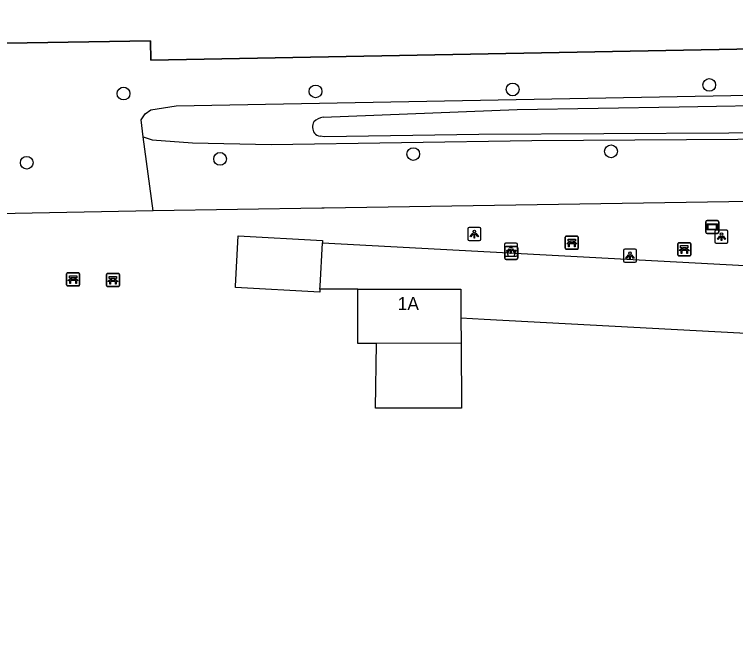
# Model space of a CAD drawing. Extents: x 161761 to 162722, y 384793 to 385405.
# Drawn here: x 162200.7 to 162256.1, y 385305.9 to 385354.5 of the extents above; entities that cross this region are included whole.
import ezdxf

# ---------------------------------------------------------------- set-up
doc = ezdxf.new("R2010")
doc.units = 0
for name, color, linetype in [('IMGEO_Afvalbak', 7, 'Continuous'), ('IMGEO_Bank', 7, 'Continuous'), ('IMGEO_Boom', 7, 'Continuous'), ('IMGEO_Groenvoorziening', 7, 'Continuous'), ('IMGEO_Hek', 7, 'Continuous'), ('IMGEO_Lichtpunt', 7, 'Continuous'), ('IMGEO_Pand', 7, 'Continuous'), ('IMGEO_Pand_nummerreeks', 7, 'Continuous'), ('IMGEO_Verklikker', 7, 'Continuous'), ('IMGEO_Voetpad_open', 7, 'Continuous'), ('IMGEO_Waterloop', 7, 'Continuous')]:
    doc.layers.add(name, color=color, linetype=linetype)

msp = doc.modelspace()

# ---------------------------------------------------------------- linework, layer by layer
at = {"layer": 'IMGEO_Afvalbak'}
for p, q in [((162238.362, 385335.756), (162238.362, 385336.556)), ((162238.362, 385336.556), (162238.362, 385335.756)), ((162238.462, 385336.656), (162239.252, 385336.656)), ((162239.252, 385336.656), (162238.462, 385336.656)), ((162239.352, 385336.556), (162239.352, 385335.756)), ((162239.352, 385335.756), (162239.352, 385336.556)), ((162239.252, 385335.656), (162238.462, 385335.656)), ((162238.462, 385335.656), (162239.252, 385335.656))]:
    msp.add_line(p, q, dxfattribs=at)
msp.add_lwpolyline([(162238.505, 385336.37), (162239.209, 385336.37), (162239.06, 385335.9), (162238.654, 385335.9), (162238.505, 385336.37)], dxfattribs=at)
for centre, start, end in [((162238.462, 385336.556), 90, 180), ((162238.462, 385336.556), 90, 180), ((162239.252, 385336.556), 0, 90), ((162239.252, 385336.556), 360, 90), ((162238.462, 385335.756), 180, 270), ((162238.462, 385335.756), 180, 270), ((162239.252, 385335.756), 270, 0), ((162239.252, 385335.756), 270, 0)]:
    msp.add_arc(centre, 0.1, start, end, dxfattribs=at)
at = {"layer": 'IMGEO_Bank'}
for p, q in [((162243.01, 385336.531), (162243.01, 385337.372)), ((162243.01, 385337.372), (162243.01, 385336.531)), ((162243.085, 385337.456), (162243.926, 385337.456)), ((162243.926, 385337.456), (162243.085, 385337.456)), ((162243.319, 385336.962), (162243.319, 385337.068)), ((162243.363, 385337.068), (162243.363, 385336.962)), ((162243.651, 385337.074), (162243.369, 385337.074)), ((162243.369, 385336.956), (162243.651, 385336.956)), ((162243.657, 385336.962), (162243.657, 385337.068)), ((162243.701, 385337.068), (162243.701, 385336.962)), ((162244.01, 385337.381), (162244.01, 385336.54)), ((162244.01, 385336.54), (162244.01, 385337.381)), ((162251.735, 385336.946), (162252.576, 385336.946)), ((162252.576, 385336.946), (162251.735, 385336.946)), ((162243.935, 385336.456), (162243.094, 385336.456)), ((162243.094, 385336.456), (162243.935, 385336.456)), ((162243.707, 385336.854), (162243.314, 385336.854)), ((162251.66, 385336.021), (162251.66, 385336.862)), ((162251.66, 385336.862), (162251.66, 385336.021)), ((162251.969, 385336.452), (162251.969, 385336.558)), ((162252.013, 385336.558), (162252.013, 385336.452)), ((162252.301, 385336.564), (162252.019, 385336.564)), ((162252.019, 385336.446), (162252.301, 385336.446)), ((162252.307, 385336.452), (162252.307, 385336.558)), ((162252.351, 385336.558), (162252.351, 385336.452)), ((162252.66, 385336.871), (162252.66, 385336.03)), ((162252.66, 385336.03), (162252.66, 385336.871)), ((162252.585, 385335.946), (162251.744, 385335.946)), ((162251.744, 385335.946), (162252.585, 385335.946)), ((162252.357, 385336.344), (162251.964, 385336.344)), ((162204.681, 385333.714), (162204.681, 385334.555)), ((162204.681, 385334.555), (162204.681, 385333.714)), ((162204.756, 385334.639), (162205.597, 385334.639)), ((162205.597, 385334.639), (162204.756, 385334.639)), ((162204.99, 385334.145), (162204.99, 385334.251)), ((162205.034, 385334.251), (162205.034, 385334.145)), ((162205.322, 385334.257), (162205.04, 385334.257)), ((162205.04, 385334.139), (162205.322, 385334.139)), ((162205.328, 385334.145), (162205.328, 385334.251)), ((162205.372, 385334.251), (162205.372, 385334.145)), ((162205.681, 385334.564), (162205.681, 385333.723)), ((162205.681, 385333.723), (162205.681, 385334.564)), ((162207.744, 385333.657), (162207.744, 385334.498)), ((162207.744, 385334.498), (162207.744, 385333.657)), ((162207.819, 385334.582), (162208.66, 385334.582)), ((162208.66, 385334.582), (162207.819, 385334.582)), ((162208.053, 385334.088), (162208.053, 385334.194)), ((162208.097, 385334.194), (162208.097, 385334.088)), ((162208.385, 385334.2), (162208.103, 385334.2)), ((162208.391, 385334.088), (162208.391, 385334.194)), ((162208.435, 385334.194), (162208.435, 385334.088)), ((162208.744, 385334.507), (162208.744, 385333.666)), ((162208.744, 385333.666), (162208.744, 385334.507)), ((162205.606, 385333.639), (162204.765, 385333.639)), ((162204.765, 385333.639), (162205.606, 385333.639)), ((162205.378, 385334.037), (162204.985, 385334.037)), ((162208.441, 385333.98), (162208.048, 385333.98)), ((162208.103, 385334.082), (162208.385, 385334.082)), ((162208.669, 385333.582), (162207.828, 385333.582)), ((162207.828, 385333.582), (162208.669, 385333.582))]:
    msp.add_line(p, q, dxfattribs=at)
for points in [[(162243.257, 385336.854), (162243.115, 385336.854), (162243.227, 385336.956), (162243.313, 385336.956)], [(162243.313, 385337.074), (162243.227, 385337.074), (162243.227, 385337.235), (162243.79, 385337.235), (162243.79, 385337.074), (162243.707, 385337.074)], [(162243.707, 385336.956), (162243.79, 385336.956), (162243.902, 385336.854), (162243.763, 385336.854)], [(162243.307, 385336.847), (162243.307, 385336.64), (162243.264, 385336.64), (162243.264, 385336.847)], [(162243.757, 385336.847), (162243.757, 385336.64), (162243.713, 385336.64), (162243.713, 385336.847)], [(162251.907, 385336.344), (162251.765, 385336.344), (162251.877, 385336.446), (162251.963, 385336.446)], [(162251.963, 385336.564), (162251.877, 385336.564), (162251.877, 385336.725), (162252.44, 385336.725), (162252.44, 385336.564), (162252.357, 385336.564)], [(162252.357, 385336.446), (162252.44, 385336.446), (162252.552, 385336.344), (162252.413, 385336.344)], [(162251.957, 385336.337), (162251.957, 385336.13), (162251.914, 385336.13), (162251.914, 385336.337)], [(162252.407, 385336.337), (162252.407, 385336.13), (162252.363, 385336.13), (162252.363, 385336.337)], [(162204.928, 385334.037), (162204.786, 385334.037), (162204.898, 385334.139), (162204.984, 385334.139)], [(162204.984, 385334.257), (162204.898, 385334.257), (162204.898, 385334.418), (162205.461, 385334.418), (162205.461, 385334.257), (162205.378, 385334.257)], [(162205.378, 385334.139), (162205.461, 385334.139), (162205.573, 385334.037), (162205.434, 385334.037)], [(162208.047, 385334.2), (162207.961, 385334.2), (162207.961, 385334.361), (162208.524, 385334.361), (162208.524, 385334.2), (162208.441, 385334.2)], [(162204.978, 385334.03), (162204.978, 385333.823), (162204.935, 385333.823), (162204.935, 385334.03)], [(162205.428, 385334.03), (162205.428, 385333.823), (162205.384, 385333.823), (162205.384, 385334.03)], [(162207.991, 385333.98), (162207.849, 385333.98), (162207.961, 385334.082), (162208.047, 385334.082)], [(162208.041, 385333.973), (162208.041, 385333.766), (162207.998, 385333.766), (162207.998, 385333.973)], [(162208.441, 385334.082), (162208.524, 385334.082), (162208.636, 385333.98), (162208.497, 385333.98)], [(162208.491, 385333.973), (162208.491, 385333.766), (162208.447, 385333.766), (162208.447, 385333.973)]]:
    msp.add_lwpolyline(points, dxfattribs=at)
for centre, radius, start, end in [((162243.088, 385337.378), 0.0779, 92.4484, 184.2845), ((162243.088, 385337.378), 0.0779, 92.4484, 184.2845), ((162243.312, 385337.067), 0.00671, 2.8957, 87.1043), ((162243.312, 385336.963), 0.00671, 272.8957, 357.1043), ((162243.369, 385337.067), 0.00671, 92.8957, 177.1043), ((162243.369, 385336.963), 0.00671, 182.8957, 267.1043), ((162243.651, 385337.067), 0.00671, 2.8957, 87.1043), ((162243.651, 385336.963), 0.00671, 272.8957, 357.1043), ((162243.708, 385337.067), 0.00671, 92.8957, 177.1043), ((162243.708, 385336.963), 0.00671, 182.8957, 267.1043), ((162243.932, 385337.378), 0.0779, 2.4484, 94.2845), ((162243.932, 385337.378), 0.0779, 2.4484, 94.2845), ((162251.738, 385336.868), 0.0779, 92.4484, 184.2845), ((162251.738, 385336.868), 0.0779, 92.4484, 184.2845), ((162252.582, 385336.868), 0.0779, 2.4484, 94.2845), ((162252.582, 385336.868), 0.0779, 2.4484, 94.2845), ((162243.088, 385336.534), 0.0779, 182.4484, 274.2845), ((162243.088, 385336.534), 0.0779, 182.4484, 274.2845), ((162243.257, 385336.847), 0.00671, 2.8957, 87.1043), ((162243.314, 385336.847), 0.00671, 92.8957, 177.1043), ((162243.706, 385336.847), 0.00671, 2.8957, 87.1043), ((162243.763, 385336.847), 0.00671, 92.8957, 177.1043), ((162243.932, 385336.534), 0.0779, 272.4484, 4.2845), ((162243.932, 385336.534), 0.0779, 272.4484, 4.2845), ((162251.962, 385336.557), 0.00671, 2.8957, 87.1043), ((162251.962, 385336.453), 0.00671, 272.8957, 357.1043), ((162252.019, 385336.557), 0.00671, 92.8957, 177.1043), ((162252.019, 385336.453), 0.00671, 182.8957, 267.1043), ((162252.301, 385336.557), 0.00671, 2.8957, 87.1043), ((162252.301, 385336.453), 0.00671, 272.8957, 357.1043), ((162252.358, 385336.557), 0.00671, 92.8957, 177.1043), ((162252.358, 385336.453), 0.00671, 182.8957, 267.1043), ((162251.738, 385336.024), 0.0779, 182.4484, 274.2845), ((162251.738, 385336.024), 0.0779, 182.4484, 274.2845), ((162251.907, 385336.337), 0.00671, 2.8957, 87.1043), ((162251.964, 385336.337), 0.00671, 92.8957, 177.1043), ((162252.356, 385336.337), 0.00671, 2.8957, 87.1043), ((162252.413, 385336.337), 0.00671, 92.8957, 177.1043), ((162252.582, 385336.024), 0.0779, 272.4484, 4.2845), ((162252.582, 385336.024), 0.0779, 272.4484, 4.2845), ((162204.759, 385334.561), 0.0779, 92.4484, 184.2845), ((162204.759, 385334.561), 0.0779, 92.4484, 184.2845), ((162204.983, 385334.25), 0.00671, 2.8957, 87.1043), ((162204.983, 385334.146), 0.00671, 272.8957, 357.1043), ((162205.04, 385334.25), 0.00671, 92.8957, 177.1043), ((162205.04, 385334.146), 0.00671, 182.8957, 267.1043), ((162205.322, 385334.25), 0.00671, 2.8957, 87.1043), ((162205.322, 385334.146), 0.00671, 272.8957, 357.1043), ((162205.379, 385334.25), 0.00671, 92.8957, 177.1043), ((162205.379, 385334.146), 0.00671, 182.8957, 267.1043), ((162205.603, 385334.561), 0.0779, 2.4484, 94.2845), ((162205.603, 385334.561), 0.0779, 2.4484, 94.2845), ((162207.822, 385334.504), 0.0779, 92.4484, 184.2845), ((162207.822, 385334.504), 0.0779, 92.4484, 184.2845), ((162208.046, 385334.193), 0.00671, 2.8957, 87.1043), ((162208.103, 385334.193), 0.00671, 92.8957, 177.1043), ((162208.385, 385334.193), 0.00671, 2.8957, 87.1043), ((162208.442, 385334.193), 0.00671, 92.8957, 177.1043), ((162208.666, 385334.504), 0.0779, 2.4484, 94.2845), ((162208.666, 385334.504), 0.0779, 2.4484, 94.2845), ((162204.759, 385333.717), 0.0779, 182.4484, 274.2845), ((162204.759, 385333.717), 0.0779, 182.4484, 274.2845), ((162204.928, 385334.03), 0.00671, 2.8957, 87.1043), ((162204.985, 385334.03), 0.00671, 92.8957, 177.1043), ((162205.377, 385334.03), 0.00671, 2.8957, 87.1043), ((162205.434, 385334.03), 0.00671, 92.8957, 177.1043), ((162205.603, 385333.717), 0.0779, 272.4484, 4.2845), ((162205.603, 385333.717), 0.0779, 272.4484, 4.2845), ((162207.822, 385333.66), 0.0779, 182.4484, 274.2845), ((162207.822, 385333.66), 0.0779, 182.4484, 274.2845), ((162207.991, 385333.973), 0.00671, 2.8957, 87.1043), ((162208.048, 385333.973), 0.00671, 92.8957, 177.1043), ((162208.046, 385334.089), 0.00671, 272.8957, 357.1043), ((162208.103, 385334.089), 0.00671, 182.8957, 267.1043), ((162208.385, 385334.089), 0.00671, 272.8957, 357.1043), ((162208.442, 385334.089), 0.00671, 182.8957, 267.1043), ((162208.44, 385333.973), 0.00671, 2.8957, 87.1043), ((162208.497, 385333.973), 0.00671, 92.8957, 177.1043), ((162208.666, 385333.66), 0.0779, 272.4484, 4.2845), ((162208.666, 385333.66), 0.0779, 272.4484, 4.2845)]:
    msp.add_arc(centre, radius, start, end, dxfattribs=at)
at = {"layer": 'IMGEO_Boom'}
for centre in [(162238.963, 385348.723), (162254.078, 385349.076), (162209.053, 385348.411), (162223.811, 385348.574), (162231.32, 385343.758), (162246.523, 385343.971), (162201.612, 385343.09), (162216.473, 385343.392)]:
    msp.add_circle(centre, 0.489, dxfattribs=at)
at = {"layer": 'IMGEO_Groenvoorziening'}
for points in [[(162399.858, 385354.488), (162376.31, 385353.749), (162286.233, 385352.376), (162211.155, 385350.962), (162211.124, 385352.462), (162147.884, 385351.44), (162146.81, 385331.678), (162145.872, 385324.819), (162142.47, 385311.424), (162141.898, 385304.88), (162139.214, 385249.548), (162133.367, 385130.823)], [(162210.576, 385345.078), (162210.407, 385346.397), (162210.716, 385346.847), (162211.162, 385347.162), (162213.09, 385347.455), (162274.995, 385348.608), (162275.287, 385348.966), (162275.287, 385349.716), (162281.73, 385349.862), (162282.898, 385349.07), (162282.9, 385348.722), (162317.058, 385348.931), (162338.302, 385349.603), (162342.162, 385349.499), (162346.62, 385349.739), (162349.881, 385349.551), (162376.626, 385350.02), (162384.936, 385350.054), (162385.489, 385349.486)], [(162210.576, 385345.078), (162211.26, 385344.857), (162214.349, 385344.623), (162220.411, 385344.502), (162240.431, 385344.814), (162280.054, 385345.054), (162305.72, 385345.824), (162336.125, 385346.248), (162349.551, 385346.758), (162366.198, 385346.97), (162385.044, 385347.432), (162385.453, 385347.799)], [(162211.326, 385339.4), (162210.576, 385345.078)], [(162280.127, 385340.465), (162224.475, 385339.604), (162224.309, 385339.601), (162211.326, 385339.4)], [(162211.326, 385339.4), (162150.256, 385338.217), (162139.817, 385130.505)]]:
    msp.add_lwpolyline(points, dxfattribs=at)
at = {"layer": 'IMGEO_Hek'}
msp.add_lwpolyline([(162147.884, 385351.44), (162211.124, 385352.462), (162211.155, 385350.962), (162286.233, 385352.376), (162376.31, 385353.749), (162399.858, 385354.488)], dxfattribs=at)
at = {"layer": 'IMGEO_Lichtpunt'}
for p, q in [((162236.421, 385338.112), (162235.613, 385338.112)), ((162236.421, 385338.112), (162235.613, 385338.112)), ((162235.519, 385338.017), (162235.519, 385337.21)), ((162235.519, 385338.017), (162235.519, 385337.21)), ((162236.515, 385337.21), (162236.515, 385338.017)), ((162236.515, 385337.21), (162236.515, 385338.017)), ((162254.514, 385337.82), (162254.514, 385337.013)), ((162254.514, 385337.82), (162254.514, 385337.013)), ((162255.416, 385337.915), (162254.608, 385337.915)), ((162255.416, 385337.915), (162254.608, 385337.915)), ((162255.51, 385337.013), (162255.51, 385337.82)), ((162255.51, 385337.013), (162255.51, 385337.82)), ((162235.613, 385337.116), (162236.421, 385337.116)), ((162235.613, 385337.116), (162236.421, 385337.116)), ((162239.233, 385336.916), (162238.425, 385336.916)), ((162239.233, 385336.916), (162238.425, 385336.916)), ((162254.608, 385336.919), (162255.416, 385336.919)), ((162254.608, 385336.919), (162255.416, 385336.919)), ((162238.331, 385336.821), (162238.331, 385336.014)), ((162238.331, 385336.821), (162238.331, 385336.014)), ((162239.327, 385336.014), (162239.327, 385336.821)), ((162239.327, 385336.014), (162239.327, 385336.821)), ((162248.383, 385336.449), (162247.575, 385336.449)), ((162248.383, 385336.449), (162247.575, 385336.449)), ((162238.425, 385335.92), (162239.233, 385335.92)), ((162238.425, 385335.92), (162239.233, 385335.92)), ((162247.481, 385336.354), (162247.481, 385335.547)), ((162247.481, 385336.354), (162247.481, 385335.547)), ((162248.477, 385335.547), (162248.477, 385336.354)), ((162248.477, 385335.547), (162248.477, 385336.354)), ((162247.575, 385335.453), (162248.383, 385335.453)), ((162247.575, 385335.453), (162248.383, 385335.453))]:
    msp.add_line(p, q, dxfattribs=at)
for points in [[(162235.893, 385337.681), (162235.932, 385337.653), (162235.744, 385337.391), (162235.706, 385337.418), (162235.893, 385337.681)], [(162235.995, 385337.633), (162236.042, 385337.633), (162236.042, 385337.311), (162235.995, 385337.311), (162235.995, 385337.633)], [(162236.105, 385337.653), (162236.143, 385337.68), (162236.33, 385337.418), (162236.291, 385337.39), (162236.105, 385337.653)], [(162254.888, 385337.484), (162254.927, 385337.456), (162254.739, 385337.194), (162254.701, 385337.221), (162254.888, 385337.484)], [(162255.1, 385337.456), (162255.138, 385337.483), (162255.325, 385337.221), (162255.286, 385337.193), (162255.1, 385337.456)], [(162254.99, 385337.436), (162255.037, 385337.436), (162255.037, 385337.114), (162254.99, 385337.114), (162254.99, 385337.436)], [(162238.705, 385336.485), (162238.744, 385336.457), (162238.556, 385336.195), (162238.518, 385336.222), (162238.705, 385336.485)], [(162238.807, 385336.437), (162238.854, 385336.437), (162238.854, 385336.115), (162238.807, 385336.115), (162238.807, 385336.437)], [(162238.917, 385336.457), (162238.955, 385336.484), (162239.142, 385336.222), (162239.103, 385336.194), (162238.917, 385336.457)], [(162247.855, 385336.018), (162247.894, 385335.99), (162247.706, 385335.728), (162247.668, 385335.755), (162247.855, 385336.018)], [(162247.957, 385335.97), (162248.004, 385335.97), (162248.004, 385335.648), (162247.957, 385335.648), (162247.957, 385335.97)], [(162248.067, 385335.99), (162248.105, 385336.017), (162248.292, 385335.755), (162248.253, 385335.727), (162248.067, 385335.99)]]:
    msp.add_lwpolyline(points, dxfattribs=at)
for centre in [(162236.018, 385337.815), (162255.013, 385337.618), (162238.83, 385336.619), (162247.98, 385336.152)]:
    msp.add_circle(centre, 0.0994, dxfattribs=at)
for centre, start, end in [((162235.613, 385338.017), 90, 180), ((162235.613, 385338.017), 90, 180), ((162236.421, 385338.017), 0, 90), ((162236.421, 385338.017), 0, 90), ((162254.608, 385337.82), 90, 180), ((162254.608, 385337.82), 90, 180), ((162255.416, 385337.82), 0, 90), ((162255.416, 385337.82), 0, 90), ((162235.613, 385337.21), 180, 270), ((162235.613, 385337.21), 180, 270), ((162236.421, 385337.21), 270, 0), ((162236.421, 385337.21), 270, 360), ((162238.425, 385336.821), 90, 180), ((162238.425, 385336.821), 90, 180), ((162239.233, 385336.821), 0, 90), ((162239.233, 385336.821), 0, 90), ((162254.608, 385337.013), 180, 270), ((162254.608, 385337.013), 180, 270), ((162255.416, 385337.013), 270, 0), ((162255.416, 385337.013), 270, 360), ((162247.575, 385336.354), 90, 180), ((162247.575, 385336.354), 90, 180), ((162248.383, 385336.354), 0, 90), ((162248.383, 385336.354), 0, 90), ((162238.425, 385336.014), 180, 270), ((162238.425, 385336.014), 180, 270), ((162239.233, 385336.014), 270, 0), ((162239.233, 385336.014), 270, 360), ((162247.575, 385335.547), 180, 270), ((162247.575, 385335.547), 180, 270), ((162248.383, 385335.547), 270, 0), ((162248.383, 385335.547), 270, 360)]:
    msp.add_arc(centre, 0.0946, start, end, dxfattribs=at)
at = {"layer": 'IMGEO_Pand'}
for points in [[(162224.155, 385333.38), (162224.142, 385333.149), (162217.656, 385333.521), (162217.662, 385333.622), (162217.855, 385337.476), (162224.348, 385337.109), (162224.339, 385336.928)], [(162224.155, 385333.38), (162224.17, 385333.623), (162224.339, 385336.928)], [(162228.492, 385329.215), (162227.065, 385329.212), (162227.072, 385333.378)], [(162227.072, 385333.378), (162234.979, 385333.373), (162234.99, 385331.156)], [(162234.99, 385331.156), (162234.998, 385329.231)], [(162234.998, 385329.231), (162228.492, 385329.215)]]:
    msp.add_lwpolyline(points, dxfattribs=at)
at = {"layer": 'IMGEO_Verklikker'}
for p, q in [((162253.909, 385338.661), (162254.699, 385338.661)), ((162254.699, 385338.661), (162253.909, 385338.661)), ((162253.809, 385337.761), (162253.809, 385338.561)), ((162253.809, 385338.561), (162253.809, 385337.761)), ((162254.799, 385338.561), (162254.799, 385337.761)), ((162254.799, 385337.761), (162254.799, 385338.561)), ((162254.699, 385337.661), (162253.909, 385337.661)), ((162253.909, 385337.661), (162254.699, 385337.661))]:
    msp.add_line(p, q, dxfattribs=at)
for points in [[(162253.91, 385338.393), (162254.698, 385338.393), (162254.698, 385337.929), (162253.91, 385337.929), (162253.91, 385338.393)], [(162253.975, 385338.328), (162253.975, 385337.994), (162254.633, 385337.994), (162254.633, 385338.328), (162253.975, 385338.328)]]:
    msp.add_lwpolyline(points, dxfattribs=at)
for centre, start, end in [((162253.909, 385338.561), 90, 180), ((162253.909, 385338.561), 90, 180), ((162254.699, 385338.561), 0, 90), ((162254.699, 385338.561), 360, 90), ((162253.909, 385337.761), 180, 270), ((162253.909, 385337.761), 180, 270), ((162254.699, 385337.761), 270, 0), ((162254.699, 385337.761), 270, 0)]:
    msp.add_arc(centre, 0.1, start, end, dxfattribs=at)
at = {"layer": 'IMGEO_Voetpad_open'}
for points in [[(162224.339, 385336.928), (162269.685, 385334.516)], [(162227.072, 385333.378), (162224.155, 385333.38)], [(162269.572, 385332.969), (162269.369, 385329.305), (162236.772, 385331.057), (162234.99, 385331.156)], [(162234.998, 385329.231), (162235.019, 385324.236), (162228.418, 385324.247), (162228.492, 385329.215)]]:
    msp.add_lwpolyline(points, dxfattribs=at)
at = {"layer": 'IMGEO_Waterloop'}
for points in [[(162224.398, 385346.596), (162239.318, 385347.175), (162251.771, 385347.393), (162269.02, 385347.694), (162274.973, 385347.719), (162275.518, 385347.774), (162275.899, 385348.209), (162275.887, 385348.625), (162275.872, 385349.134), (162279.818, 385349.243), (162281.859, 385349.134), (162282.304, 385348.718), (162282.703, 385348.345), (162282.866, 385347.991), (162287.166, 385348.127), (162307.576, 385348.323), (162323.198, 385348.502), (162338.294, 385348.997), (162351.286, 385348.992), (162353.153, 385349.249), (162358.001, 385349.112), (162373.931, 385349.337), (162383.565, 385349.579)], [(162283.34, 385345.718), (162274.802, 385345.457), (162236.361, 385345.265), (162224.504, 385345.093), (162224.163, 385345.139)]]:
    msp.add_lwpolyline(points, dxfattribs=at)
for centre, radius, start, end in [((162224.565, 385345.346), 1.261, 97.6286, 134.8649), ((162224.463, 385345.845), 0.881, 153.3733, 213.0371), ((162224.238, 385345.821), 0.686, 221.6578, 263.7564)]:
    msp.add_arc(centre, radius, start, end, dxfattribs=at)

# ---------------------------------------------------------------- texts
at = {"layer": 'IMGEO_Pand_nummerreeks'}
msp.add_text('1A', height=1, dxfattribs=at).set_placement((162230.125, 385331.776))

doc.saveas('drawing.dxf')
